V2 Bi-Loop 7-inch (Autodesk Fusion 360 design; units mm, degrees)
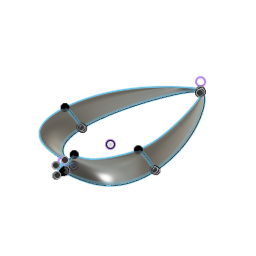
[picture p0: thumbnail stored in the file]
sketch "Hub 5mm Shaft" plane through (0, 0, 0) normal (0, 0, 1) x axis (1, 0, 0)
  circle C1 centre (0, 0) radius 6.5
  circle C2 centre (0, 0) radius 2.5
  point P1 (0, 0)
  point P2 (0, 0)
  point P3 (0, 0)
  coincident P1 P2
  coincident P1 P3
  dimension "d1" diameter C1 = 13
  dimension "d2" diameter C2 = 5
extrude "Extrude1" new body sketch "Hub 5mm Shaft" along normal blind 6 bodies "Hub 5mm Shaft"
sketch "Start Profile" plane through (0, 0, 0) normal (1, 0, 0) x axis (0, 1, 0)
  line L1 (-1.2, 0) -> (0, 0)
  line L2 (-5, 0) -> (-5.9, 0)
  curve K1 (-5, 0) -> (-5.9, 0)
  curve K2 (0, 0) -> (-1.2, 0)
  curve K3 (6.385, 6) -> (5.615, 6)
  curve K4 (0.3, 6) -> (-0.3, 6)
  curve K5 (-1, -1.5) -> (1, 1.5)
  curve K6 (-6, -1.5) -> (-4, 1.5)
  curve K7 (-4.9, 1.5) -> (-6.9, -1.5)
  curve K8 (-0.2, 1.5) -> (-2.2, -1.5)
  point P1 (0, 0)
  point P2 (0, 0)
  point P6 (0, 0)
  point P3 (6, 6)
  point P4 (0, 6)
  point P8 (-5, 0)
  point P5 (-5.9, 0)
  point P7 (-1.2, 0)
  point P9 (5.615, 6)
  point P10 (6.385, 6)
  point P11 (-0.3, 6)
  point P12 (0.3, 6)
  point P21 (0, 0)
  point P24 (0, 0)
  coincident P1 P2
  coincident P1 P6
  horizontal L1
  horizontal L2
  midpoint P3 K3
  midpoint P4 K4
  midpoint P2 K5
  midpoint P8 K6
  midpoint P5 K7
  midpoint P7 K8
  dimension "d5" distance P2 P7 = 1.2
  dimension "d6" distance P5 P8 = 0.9
  dimension "d7" distance P2 P8 = 5
  dimension "d8" distance P4 P5 = 5.9
  dimension "d9" distance P2 P4 = 6
  dimension "d10" distance P2 P3 = 6
  dimension "d11" distance P2 P3 = 6
  dimension "d12" distance P9 P10 = 0.77
  dimension "d13" distance P11 P12 = 0.6
  dimension "d17" distance P21 = 88.9 (= "( 177.8 / 2 ) * 1 mm")
  dimension "d38" distance P24 = 29.6333 (= "( 177.8 / 3 / 2 ) * 1 mm")
  dimension "d46" distance P24 = 29.6333 (= "( 177.8 / 2 / 3 ) * 1 mm")
sketch "Edge Profile" plane through (0, 0, 0) normal (1, 0, 0) x axis (0, 1, 0)
  line L1 (87.8, 0) -> (88.9, 0)
  curve K1 (87.8, 0) -> (88.9, 0)
  curve K2 (88.9, 1) -> (88.9, -1)
  curve K3 (87.8, -1) -> (87.8, 1)
  curve K4 (88.1, 1.5) -> (88.7, 1.5)
  point P2 (88.9, 0)
  point P3 (87.8, 0)
  point P4 (88.4, 1.5)
  point P9 (0, 0)
  point P10 (88.7, 1.5)
  point P11 (88.1, 1.5)
  point P1 (0, 0)
  horizontal L1
  midpoint P2 K2
  midpoint P3 K3
  midpoint P4 K4
  dimension "d14" distance P2 P3 = 1.1
  dimension "d16" distance P2 P4 = 0.5
  dimension "d17" distance P2 P9 = 88.9 (= "( 177.8 / 2 ) * 1 mm")
  dimension "d18" distance P10 P11 = 0.6
  dimension "d96" distance P1 P4 = 1.5
sketch "Target Rail" plane through (0, 0, 0) normal (0, 0, 1) x axis (1, 0, 0)
  line L1 (0, -1.2) -> (0, 0)
  line L2 (0, 21.1667) -> (0, 0)
  line L3 (21.1667, 21.1667) -> (0, 21.1667)
  line L4 (-21.1667, 21.1667) -> (0, 21.1667)
  circle C1 centre (0, 0) radius 63.5
  point P1 (0, 0)
  point P2 (0, 0)
  point P5 (0, 0)
  point P6 (0, 21.1667)
  point P7 (21.1667, 21.1667)
  point P8 (-21.1667, 21.1667)
  coincident P1 P2
  coincident P1 P5
  parallel L1 L2
  perpendicular L2 L3
  perpendicular L2 L4
  dimension "d19" diameter C1 = 127
  dimension "d20" distance P5 P6 = 21.1667 (= "( ( 127 / 2 ) / 3 ) * 1 mm")
  dimension "d21" distance P6 P7 = 21.1667 (= "( ( 127 / 2 ) / 3 ) * 1 mm")
  dimension "d22" distance P6 P8 = 21.1667 (= "( 127 / 2 / 3 ) * 1 mm")
work_plane "WorkPlane1" AlongDistance 29.6333 (= "( 177.8 / 2 / 3 ) * 1 mm")
sketch "Mid Profile" plane through (0, 29.6333, 0) normal (0, 1, 0) x axis (1, 0, 0)
  curve K1 (28.4333, 0) -> (29.6333, 0)
  curve K2 (27.451, -2) -> (31.8156, 2)
  curve K3 (17.7542, -5.925) -> (18.5125, -6.075)
  curve K4 (31.3, 2) -> (25.5667, -2)
  line L1 (28.4333, 0) -> (29.6333, 0)
  line L2 (-19.3333, 0) -> (-18.1333, 0)
  curve K5 (-19.3333, 0) -> (-18.1333, 0)
  curve K6 (-20.4875, -2) -> (-15.7792, 2)
  curve K7 (-29.9708, -5.95) -> (-29.2958, -6.05)
  curve K8 (-16.4667, 2) -> (-22.2, -2)
  point P2 (0, 0)
  point P4 (29.6333, 0)
  point P6 (18.1333, -6)
  point P13 (-29.6333, -6)
  point P16 (-18.1333, 0)
  point P18 (-19.3333, 0)
  point P7 (28.4333, 0)
  dimension "d38" distance P2 P4 = 29.6333 (= "( 177.8 / 3 / 2 ) * 1 mm")
  dimension "d39" distance P4 P6 = 11.5
  dimension "d40" distance P4 P6 = 6
  dimension "d42" distance P13 P16 = 11.5
  dimension "d43" distance P13 P16 = 6
  dimension "d46" distance P2 P13 = 29.6333 (= "( 177.8 / 2 / 3 ) * 1 mm")
  dimension "d47" distance P16 P18 = 1.2
  dimension "d84" distance P4 P7 = 1.2
sketch "End Profile" plane through (0, 0, 0) normal (1, 0, 0) x axis (0, 1, 0)
  line L1 (4.5636, 0) -> (5.7636, 0)
  curve K1 (0, 0) -> (0.8, 0)
  curve K2 (-0.2, 1.5) -> (1.8, -1.5)
  curve K3 (-6.25, 6) -> (-5.75, 6)
  curve K4 (1, -1.5) -> (-1, 1.5)
  line L2 (0.8, 0) -> (-0.0364, 0)
  curve K5 (4.5636, 0) -> (5.7636, 0)
  curve K6 (4.7818, 1.5) -> (6.7818, -1.5)
  curve K7 (-0.2864, 6) -> (0.4136, 6)
  curve K8 (5.7818, -1.5) -> (3.7818, 1.5)
  line L3 (-6.25, 6) -> (-5.75, 6)
  line L4 (-0.2864, 6) -> (0.4136, 6)
  point P2 (0, 0)
  point P11 (0.8, 0)
  point P14 (4.5636, 0)
  point P20 (5.7636, 0)
  point P5 (-0.0364, 0)
  point P6 (-0.0364, 6)
  point P12 (-0.0364, 0)
  point P18 (-6, 6)
  point P7 (-6.25, 6)
  point P23 (-5.75, 6)
  point P3 (0.4136, 6)
  point P17 (-0.2864, 6)
  dimension "d57" distance P2 P11 = 0.8
  dimension "d58" distance P14 P20 = 1.2
  dimension "d59" distance P5 P20 = 5.8
  dimension "d60" distance P6 P12 = 6
  dimension "d61" distance P6 P20 = 5.8
  dimension "d62" distance P11 P18 = 6.8
  dimension "d63" distance P2 P7 = 6
  dimension "d65" distance P7 P23 = 0.5
  dimension "d66" distance P3 P17 = 0.7
  dimension "d67" distance P6 P17 = 0.25
sketch "Lower Rails" plane through (0, 0, 0) normal (0, 0, 1) x axis (1, 0, 0)
  curve K1 (0, 4.5636) -> (0, -1.2)
  curve K2 (0, 0) -> (0, 5.7636)
  curve K3 (-7, 0) -> (7, 0)
  curve K4 (8, -1) -> (-8, -1.4)
  curve K5 (-3, 5.7636) -> (3, 5.7636)
  curve K6 (3.693, 4.6415) -> (-3.693, 4.4857)
  curve K7 (-18.4346, 41.0116) -> (-17.8321, 18.2551)
  curve K8 (-19.0325, 18.2694) -> (-19.6342, 40.9972)
  curve K9 (-2, 88.9) -> (2, 88.9)
  curve K10 (1.7, 87.8) -> (-1.7, 87.8)
  curve K11 (29, 40) -> (30.2667, 19.2667)
  curve K12 (29, 20.0333) -> (27.8667, 39.2333)
  point P2 (0, -1.2)
  point P7 (0, -1.2)
  point P3 (29.6333, 29.6333)
  point P8 (29.6333, 29.6333)
  point P4 (0, 88.9)
  point P9 (0, 88.9)
  point P5 (-19.3333, 29.6333)
  point P10 (-19.3333, 29.6333)
  point P11 (0, 5.7636)
  point P16 (0, 5.7636)
  point P12 (-18.1333, 29.6333)
  point P17 (-18.1333, 29.6333)
  point P13 (0, 87.8)
  point P18 (0, 87.8)
  point P14 (28.4333, 29.6333)
  point P19 (28.4333, 29.6333)
  point P1 (0, 0)
  point P15 (0, 0)
  point P6 (0, 4.5636)
  point P36 (0, 4.5636)
  coincident P2 P7
  coincident P3 P8
  coincident P4 P9
  coincident P5 P10
  coincident P11 P16
  coincident P12 P17
  coincident P13 P18
  coincident P14 P19
  coincident P1 P15
  midpoint P15 K3
  midpoint P2 K4
  midpoint P11 K5
  midpoint P6 K6
  midpoint P12 K7
  midpoint P5 K8
  parallel K7 K8
  midpoint P4 K9
  midpoint P13 K10
  coincident P6 P36
  midpoint P3 K11
  midpoint P14 K12
work_plane "WorkPlane2" AlongDistance 6
sketch "Upper Rails" plane through (0, 0, 6) normal (0, 0, 1) x axis (1, 0, 0)
  curve K1 (0, 0) -> (0, 6)
  curve K2 (5.5, 0) -> (-5.5, 0)
  curve K3 (7, 6) -> (-7, 6)
  curve K4 (19.0059, 36.9233) -> (17.2607, 22.3434)
  curve K5 (-29.8079, 17.7839) -> (-29.4588, 41.4828)
  curve K6 (-1.75, 88.35) -> (1.75, 88.35)
  point P2 (0, 6)
  point P7 (0, 6)
  point P3 (18.1333, 29.6333)
  point P8 (18.1333, 29.6333)
  point P5 (-29.6333, 29.6333)
  point P10 (-29.6333, 29.6333)
  point P6 (0, 0)
  point P4 (0, 88.35)
  coincident P2 P7
  coincident P3 P8
  coincident P5 P10
  midpoint P6 K2
  midpoint P2 K3
  midpoint P3 K4
  midpoint P5 K5
  midpoint P4 K6
loft "Loft1" sketch "Start Profile" + "Mid Profile" bodies "Template 1 6x3x2"
loft "Loft3" sketch "Mid Profile" + "Edge Profile"
loft "Loft2" sketch "Mid Profile" + "End Profile"
loft "Loft4" sketch "Mid Profile"
circular_pattern "C-Pattern1" TotalAngle 360 bodies "Template 2 6x3x2"
sketch "Blade Trimmer" plane through (0, 0, 0) normal (0, 0, 1) x axis (1, 0, 0)
  circle C1 centre (0, 0) radius 3
  point P1 (0, 0)
  point P2 (0, 0)
  coincident P1 P2
  dimension "d71" diameter C1 = 6
extrude "Extrude2" cut sketch "Blade Trimmer" along normal blind 14
copy_paste_bodies "CopyPasteBodies1"
chamfer "Start Profile" distance 0.5
offset_faces "OffsetFaces1" distance 2
combine "Start Profile"
fillet "Fillet2" radius 1
offset_faces "OffsetFaces2" distance -2
sketch "Fillet Trimmer" plane through (0, 0, 6) normal (0, 0, 1) x axis (-1, 0, 0)
  curve K1 (0.6833, 6.464) -> (5.5929, 3.3121)
  curve K2 (-29.6333, 29.6333) -> (-6.4138, 1.0553)
  curve K3 (-0.6833, -6.464) -> (-5.5929, -3.3121)
  curve K4 (29.6333, -29.6333) -> (6.4138, -1.0553)
  curve K5 (-6.4968, -0.2036) -> (-29.6333, 29.6333)
  curve K6 (6.4968, 0.2036) -> (29.6333, -29.6333)
  arc A1 centre (0, 0) radius 6.5 clockwise from (-6.4138, 1.0553) to (0.6833, 6.464)
  circle C1 centre (0, 0) radius 3
  circle C2 centre (0, 0) radius 7.5
  arc A2 centre (0, 0) radius 6.5 clockwise from (-5.5929, -3.3121) to (-6.4968, -0.2036)
  arc A3 centre (0, 0) radius 6.5 clockwise from (6.4138, -1.0553) to (-0.6833, -6.464)
  arc A4 centre (0, 0) radius 6.5 clockwise from (5.5929, 3.3121) to (6.4968, 0.2036)
  point P1 (0, 0)
  point P5 (0, 0)
  coincident P1 P5
  dimension "d79" diameter C2 = 15
extrude "Extrude3" cut sketch "Fillet Trimmer" profile of A1 C1 C2 along normal blind 5
mirror "Mirror1" mirrorStitchTolerance 0.1 bodies "6x3x2 CW"
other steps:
base_feature "Base Feature" bodies "Hub 5mm Shaft", "6x3x2 CCW"
named bodies: "Hub 5mm Shaft", "Template 1 6x3x2", "Template 2 6x3x2", "6x3x2 CCW", "6x3x2 CW"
